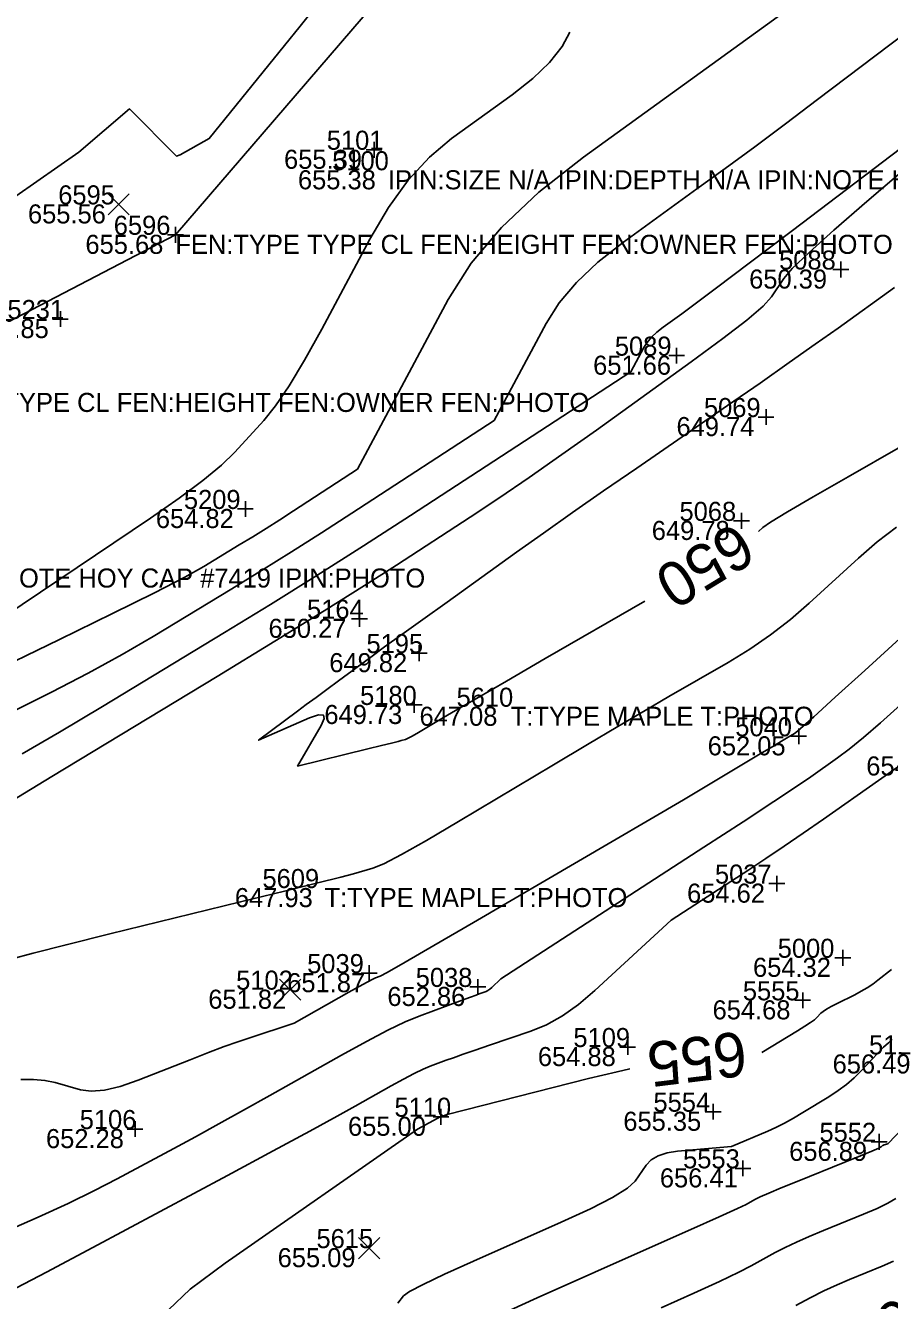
# Model space of a CAD drawing. Extents: x 2129350 to 2137777, y 657588 to 659885.
# Drawn here: x 2132874.7 to 2132929.2, y 658364.2 to 658444.5 of the extents above; entities that cross this region are included whole.
import ezdxf

# ---------------------------------------------------------------- set-up
doc = ezdxf.new("R2010")
doc.units = 0
for name, color, linetype in [('DT_X_Contour_Major', 7, 'Continuous'), ('DT_X_Contour_Minor', 7, 'Continuous'), ('DT_X_TIN_Hull', 7, 'Continuous'), ('SV_X_Random_Point', 7, 'Continuous'), ('SV_X_Shot_Marker', 7, 'Continuous'), ('SV_X_Text_Comment', 7, 'Continuous'), ('SV_X_Text_Elevation', 7, 'Continuous'), ('SV_X_Text_Name', 7, 'Continuous')]:
    doc.layers.add(name, color=color, linetype=linetype)

msp = doc.modelspace()

# ---------------------------------------------------------------- linework, layer by layer
at = {"layer": 'DT_X_Contour_Major'}
for points in [[(2132909.034, 658444.103), (2132908.549, 658443.199), (2132907.762, 658442.202), (2132906.717, 658441.189), (2132905.412, 658440.162), (2132901.587, 658437.401), (2132900.19, 658436.228), (2132898.866, 658434.783), (2132897.617, 658433.064), (2132896.442, 658431.072), (2132893.407, 658425.396), (2132892.326, 658423.439), (2132891.358, 658421.829), (2132890.503, 658420.563), (2132889.761, 658419.643), (2132887.935, 658417.651), (2132887.089, 658416.83), (2132885.919, 658415.864), (2132884.427, 658414.752), (2132882.612, 658413.493), (2132873.389, 658407.28)], [(2132929.501, 658428.031), (2132925.944, 658425.468), (2132924.508, 658424.442), (2132922.869, 658423.287), (2132921.027, 658422.002), (2132918.981, 658420.588), (2132913.255, 658416.643), (2132911.171, 658415.202), (2132909.214, 658413.838), (2132907.384, 658412.55), (2132905.681, 658411.338), (2132901.309, 658408.207), (2132899.778, 658407.11), (2132898.467, 658406.166), (2132897.374, 658405.374), (2132896.501, 658404.736), (2132894.463, 658403.238), (2132893.729, 658402.697), (2132893.054, 658402.199), (2132892.438, 658401.742), (2132891.882, 658401.328), (2132889.427, 658399.493), (2132892.642, 658400.906), (2132893.204, 658401.103), (2132893.515, 658401.087), (2132893.573, 658400.859), (2132893.38, 658400.419), (2132891.888, 658397.868), (2132896.324, 658398.954), (2132897.168, 658399.16), (2132897.799, 658399.316), (2132898.216, 658399.421), (2132898.42, 658399.474), (2132898.679, 658399.547), (2132898.824, 658399.607), (2132899.062, 658399.73), (2132899.395, 658399.918), (2132899.821, 658400.169), (2132901.085, 658400.925), (2132901.84, 658401.37), (2132903.159, 658402.138), (2132905.042, 658403.229), (2132907.487, 658404.643), (2132913.765, 658408.269)], [(2132920.925, 658412.642), (2132921.198, 658412.891), (2132921.693, 658413.236), (2132922.754, 658413.886), (2132924.382, 658414.842), (2132926.576, 658416.102), (2132933.185, 658419.871)], [(2132921.145, 658379.818), (2132923.388, 658381.188), (2132923.849, 658381.476), (2132924.207, 658381.711), (2132924.46, 658381.893), (2132924.609, 658382.023), (2132924.868, 658382.299), (2132925.004, 658382.415), (2132925.22, 658382.557), (2132925.516, 658382.724), (2132925.891, 658382.917), (2132926.996, 658383.467), (2132927.399, 658383.679), (2132927.777, 658383.901), (2132928.131, 658384.136), (2132928.46, 658384.381), (2132929.306, 658385.05)], [(2132883.761, 658363.616), (2132885.126, 658364.908), (2132887.315, 658366.547), (2132899.451, 658375.001), (2132900.909, 658375.784), (2132900.919, 658375.789), (2132900.955, 658375.801), (2132901.317, 658375.924), (2132910.219, 658378.182), (2132912.019, 658378.616), (2132912.833, 658378.788)]]:
    msp.add_lwpolyline(points, dxfattribs=at)
at = {"layer": 'DT_X_Contour_Minor'}
for points in [[(2132892.982, 658445.64), (2132892.047, 658444.483), (2132891.058, 658443.26), (2132886.32, 658437.401), (2132884.495, 658436.388), (2132884.255, 658436.304), (2132881.291, 658439.27), (2132878.094, 658436.551), (2132864.847, 658427.298)], [(2132922.872, 658445.608), (2132920.747, 658444.066), (2132918.013, 658442.089), (2132909.908, 658436.239), (2132907.096, 658434.034), (2132904.737, 658431.803), (2132902.832, 658429.549), (2132901.381, 658427.27), (2132895.666, 658416.58), (2132891.627, 658413.948), (2132890.765, 658413.39), (2132889.91, 658412.847), (2132889.06, 658412.318), (2132888.217, 658411.802), (2132885.977, 658410.446), (2132884.779, 658409.777), (2132882.863, 658408.787), (2132880.229, 658407.477), (2132876.878, 658405.845), (2132866.986, 658401.067)], [(2132930.152, 658444.03), (2132924.654, 658439.863), (2132922.632, 658438.339), (2132920.692, 658436.892), (2132918.832, 658435.522), (2132917.053, 658434.229), (2132912.419, 658430.884), (2132910.81, 658429.622), (2132909.461, 658428.347), (2132908.372, 658427.057), (2132907.541, 658425.754), (2132904.273, 658419.64), (2132895.316, 658413.801), (2132893.404, 658412.565), (2132891.506, 658411.36), (2132889.622, 658410.186), (2132887.752, 658409.043), (2132882.784, 658406.034), (2132880.832, 658404.892), (2132878.7, 658403.719), (2132876.39, 658402.518), (2132873.901, 658401.287)], [(2132937.291, 658442.399), (2132923.065, 658431.62), (2132920.343, 658429.559), (2132918.274, 658427.997), (2132916.858, 658426.934), (2132916.094, 658426.369), (2132914.929, 658425.528), (2132914.524, 658425.21), (2132914.185, 658424.89), (2132913.911, 658424.565), (2132913.702, 658424.238), (2132912.88, 658422.7), (2132899.005, 658413.654), (2132896.043, 658411.74), (2132893.102, 658409.873), (2132890.183, 658408.054), (2132887.287, 658406.283), (2132879.591, 658401.623), (2132876.885, 658400.006), (2132874.538, 658398.651)], [(2132933.961, 658438.742), (2132927.752, 658433.434), (2132925.679, 658431.638), (2132924.115, 658430.231), (2132923.062, 658429.213), (2132922.518, 658428.584), (2132921.748, 658427.426), (2132921.216, 658426.845), (2132920.196, 658425.97), (2132918.688, 658424.8), (2132916.692, 658423.337), (2132910.72, 658419.042), (2132908.542, 658417.49), (2132906.49, 658416.058), (2132904.563, 658414.745), (2132902.76, 658413.551), (2132898.12, 658410.526), (2132896.108, 658409.237), (2132893.555, 658407.641), (2132890.459, 658405.736), (2132886.821, 658403.523), (2132876.398, 658397.211), (2132872.938, 658395.121)], [(2132873.823, 658385.71), (2132875.222, 658386.088), (2132877.299, 658386.617), (2132880.053, 658387.297), (2132888.3, 658389.315), (2132891.064, 658389.993), (2132893.169, 658390.514), (2132894.617, 658390.88), (2132895.406, 658391.088), (2132896.632, 658391.435), (2132897.315, 658391.717), (2132898.443, 658392.301), (2132900.017, 658393.189), (2132902.036, 658394.379), (2132908.014, 658397.957), (2132910.15, 658399.232), (2132912.074, 658400.372), (2132913.787, 658401.379), (2132915.288, 658402.252), (2132919.01, 658404.402), (2132920.377, 658405.24), (2132921.686, 658406.142), (2132922.937, 658407.108), (2132924.13, 658408.138), (2132927.236, 658410.97), (2132928.413, 658411.989), (2132929.616, 658412.924)], [(2132874.445, 658378.115), (2132875.249, 658378.128), (2132875.971, 658378.068), (2132876.61, 658377.932), (2132878.203, 658377.473), (2132878.88, 658377.383), (2132879.713, 658377.455), (2132880.704, 658377.691), (2132881.853, 658378.09), (2132885.125, 658379.371), (2132886.275, 658379.816), (2132887.272, 658380.192), (2132888.117, 658380.499), (2132888.808, 658380.736), (2132891.677, 658381.678), (2132895.118, 658383.616), (2132895.777, 658383.985), (2132896.278, 658384.259), (2132896.621, 658384.439), (2132896.806, 658384.526), (2132897.091, 658384.631), (2132897.539, 658384.873), (2132898.669, 658385.518), (2132900.481, 658386.568), (2132902.975, 658388.021), (2132916.208, 658395.746), (2132920.935, 658398.575), (2132921.83, 658399.11), (2132922.487, 658399.503), (2132922.907, 658399.754), (2132923.09, 658399.862), (2132923.26, 658399.96), (2132923.581, 658400.234), (2132924.415, 658400.981), (2132925.763, 658402.202), (2132927.625, 658403.897), (2132933.274, 658409.048)], [(2132873.449, 658368.531), (2132875.547, 658369.455), (2132877.426, 658370.32), (2132879.087, 658371.125), (2132880.53, 658371.87), (2132884.085, 658373.776), (2132885.464, 658374.521), (2132886.932, 658375.325), (2132888.489, 658376.189), (2132890.137, 658377.113), (2132894.649, 658379.654), (2132896.225, 658380.523), (2132897.567, 658381.224), (2132898.677, 658381.758), (2132899.553, 658382.123), (2132902.257, 658383.124), (2132902.775, 658383.314), (2132903.134, 658383.445), (2132903.331, 658383.515), (2132903.645, 658383.621), (2132903.763, 658383.67), (2132903.883, 658383.737), (2132904.004, 658383.823), (2132904.127, 658383.928), (2132904.703, 658384.459), (2132917.479, 658392.756), (2132919.954, 658394.367), (2132921.903, 658395.644), (2132923.325, 658396.589), (2132924.222, 658397.199), (2132925.912, 658398.384), (2132926.635, 658398.926), (2132927.538, 658399.666), (2132928.62, 658400.603), (2132929.881, 658401.736)], [(2132873.685, 658364.746), (2132876.068, 658365.983), (2132878.982, 658367.532), (2132887.463, 658372.08), (2132890.351, 658373.632), (2132892.657, 658374.877), (2132894.379, 658375.815), (2132895.519, 658376.446), (2132897.779, 658377.719), (2132898.569, 658378.154), (2132899.241, 658378.506), (2132899.797, 658378.773), (2132900.236, 658378.956), (2132901.25, 658379.331), (2132901.706, 658379.496), (2132902.312, 658379.709), (2132903.068, 658379.969), (2132903.974, 658380.277), (2132906.59, 658381.163), (2132907.578, 658381.572), (2132908.578, 658382.136), (2132909.591, 658382.855), (2132910.617, 658383.729), (2132915.435, 658388.166), (2132920.324, 658391.342), (2132921.403, 658392.051), (2132922.546, 658392.818), (2132923.751, 658393.642), (2132925.018, 658394.523), (2132928.483, 658396.951), (2132929.683, 658397.805)], [(2132929.346, 658380.644), (2132929.112, 658380.443), (2132928.812, 658380.152), (2132928.447, 658379.772), (2132927.386, 658378.64), (2132926.961, 658378.222), (2132926.482, 658377.816), (2132925.949, 658377.422), (2132925.362, 658377.041), (2132923.726, 658376.041), (2132923.127, 658375.687), (2132922.559, 658375.374), (2132922.022, 658375.104), (2132921.516, 658374.875), (2132919.225, 658373.903), (2132915.835, 658373.605), (2132915.167, 658373.502), (2132914.614, 658373.321), (2132914.177, 658373.061), (2132913.857, 658372.723), (2132913.157, 658371.718), (2132912.668, 658371.274), (2132911.728, 658370.694), (2132910.337, 658369.979), (2132908.495, 658369.129), (2132902.979, 658366.682), (2132901.152, 658365.857), (2132899.809, 658365.217), (2132898.948, 658364.763), (2132898.57, 658364.494), (2132898.206, 658364.024)], [(2132931.643, 658376.746), (2132929.074, 658374.066), (2132928.858, 658374.005), (2132928.815, 658373.991), (2132928.778, 658373.974), (2132928.747, 658373.956), (2132928.722, 658373.934), (2132928.663, 658373.875), (2132928.504, 658373.799), (2132928.069, 658373.614), (2132927.358, 658373.321), (2132926.372, 658372.92), (2132923.376, 658371.706), (2132922.366, 658371.293), (2132921.585, 658370.964), (2132921.031, 658370.721), (2132920.706, 658370.562), (2132920.143, 658370.251), (2132919.616, 658369.998), (2132918.461, 658369.471), (2132916.675, 658368.67), (2132914.26, 658367.596), (2132906.98, 658364.366), (2132904.556, 658363.26)], [(2132929.574, 658370.617), (2132929.078, 658370.329), (2132928.402, 658370.003), (2132927.546, 658369.639), (2132925.024, 658368.617), (2132924.125, 658368.242), (2132923.32, 658367.885), (2132922.609, 658367.545), (2132921.991, 658367.221), (2132920.47, 658366.382), (2132919.687, 658365.981), (2132918.479, 658365.407), (2132916.847, 658364.66), (2132914.79, 658363.739)], [(2132929.446, 658366.686), (2132928.72, 658366.359), (2132926.672, 658365.529), (2132925.884, 658365.192), (2132925.055, 658364.806), (2132924.186, 658364.368), (2132923.277, 658363.881)]]:
    msp.add_lwpolyline(points, dxfattribs=at)
at = {"layer": 'DT_X_TIN_Hull'}
msp.add_lwpolyline([(2132540.53, 658289.401), (2132539.033, 658286.057), (2132536.832, 658279.3), (2132537.201, 658279.007), (2132540.621, 658270.415), (2132548.203, 658269.845), (2132579.386, 658310.868), (2132621.001, 658329.414), (2132667.619, 658335.399), (2132712.749, 658350.209), (2132765.513, 658370.931), (2132811.121, 658416.764), (2132865.063, 658421.381), (2132884.187, 658431.342), (2132933.332, 658488.426), (2132983.351, 658480.409), (2133063.13, 658518.414), (2133131.969, 658559.405), (2133180.891, 658556.239), (2133241.37, 658575.534)], dxfattribs=at)
at = {"layer": 'SV_X_Random_Point'}
for p, q in [((2132879.948, 658432.59), (2132881.282, 658433.926)), ((2132879.948, 658433.926), (2132881.282, 658432.59)), ((2132890.752, 658383.115), (2132892.086, 658384.451)), ((2132890.752, 658384.451), (2132892.086, 658383.115)), ((2132895.728, 658366.833), (2132897.062, 658368.167)), ((2132895.728, 658368.167), (2132897.062, 658366.833))]:
    msp.add_line(p, q, dxfattribs=at)
at = {"layer": 'SV_X_Shot_Marker'}
for p, q in [((2132896.704, 658437.2), (2132896.704, 658436.2)), ((2132896.204, 658436.7), (2132897.204, 658436.7)), ((2132896.704, 658436.7), (2132896.704, 658436.7)), ((2132883.689, 658431.342), (2132884.689, 658431.342)), ((2132884.189, 658431.842), (2132884.189, 658430.842)), ((2132884.189, 658431.342), (2132884.189, 658431.342)), ((2132926.123, 658429.654), (2132926.123, 658428.654)), ((2132925.623, 658429.154), (2132926.623, 658429.154)), ((2132926.123, 658429.154), (2132926.123, 658429.154)), ((2132876.942, 658426.536), (2132876.942, 658425.536)), ((2132876.442, 658426.036), (2132877.442, 658426.036)), ((2132876.942, 658426.036), (2132876.942, 658426.036)), ((2132915.772, 658424.228), (2132915.772, 658423.228)), ((2132915.272, 658423.728), (2132916.272, 658423.728)), ((2132915.772, 658423.728), (2132915.772, 658423.728)), ((2132921.404, 658420.36), (2132921.404, 658419.36)), ((2132920.904, 658419.86), (2132921.904, 658419.86)), ((2132921.404, 658419.86), (2132921.404, 658419.86)), ((2132888.599, 658414.568), (2132888.599, 658413.568)), ((2132888.099, 658414.068), (2132889.099, 658414.068)), ((2132888.599, 658414.068), (2132888.599, 658414.068)), ((2132919.864, 658413.816), (2132919.864, 658412.816)), ((2132919.364, 658413.316), (2132920.364, 658413.316)), ((2132919.864, 658413.316), (2132919.864, 658413.316)), ((2132895.29, 658407.15), (2132896.29, 658407.15)), ((2132895.79, 658407.65), (2132895.79, 658406.65)), ((2132895.79, 658407.15), (2132895.79, 658407.15)), ((2132899.544, 658405.487), (2132899.544, 658404.487)), ((2132899.044, 658404.987), (2132900.044, 658404.987)), ((2132899.544, 658404.987), (2132899.544, 658404.987)), ((2132898.728, 658401.721), (2132899.728, 658401.721)), ((2132899.228, 658402.221), (2132899.228, 658401.221)), ((2132899.228, 658401.721), (2132899.228, 658401.721)), ((2132923.464, 658400.247), (2132923.464, 658399.247)), ((2132922.964, 658399.747), (2132923.964, 658399.747)), ((2132923.464, 658399.747), (2132923.464, 658399.747)), ((2132921.588, 658390.465), (2132922.588, 658390.465)), ((2132922.088, 658390.965), (2132922.088, 658389.965)), ((2132922.088, 658390.465), (2132922.088, 658390.465)), ((2132926.244, 658386.291), (2132926.244, 658385.291)), ((2132925.744, 658385.791), (2132926.744, 658385.791)), ((2132926.244, 658385.791), (2132926.244, 658385.791)), ((2132895.904, 658384.825), (2132896.904, 658384.825)), ((2132896.404, 658385.325), (2132896.404, 658384.325)), ((2132896.404, 658384.825), (2132896.404, 658384.825)), ((2132902.744, 658383.955), (2132903.744, 658383.955)), ((2132903.244, 658384.455), (2132903.244, 658383.455)), ((2132903.244, 658383.955), (2132903.244, 658383.955)), ((2132923.215, 658383.112), (2132924.215, 658383.112)), ((2132923.715, 658383.612), (2132923.715, 658382.612)), ((2132923.715, 658383.112), (2132923.715, 658383.112)), ((2132912.688, 658380.669), (2132912.688, 658379.669)), ((2132912.188, 658380.169), (2132913.188, 658380.169)), ((2132912.688, 658380.169), (2132912.688, 658380.169)), ((2132918.072, 658376.593), (2132918.072, 658375.593)), ((2132900.422, 658375.776), (2132901.422, 658375.776)), ((2132900.922, 658376.276), (2132900.922, 658375.276)), ((2132900.922, 658375.776), (2132900.922, 658375.776)), ((2132917.572, 658376.093), (2132918.572, 658376.093)), ((2132918.072, 658376.093), (2132918.072, 658376.093)), ((2132881.147, 658375.001), (2132882.147, 658375.001)), ((2132881.647, 658375.501), (2132881.647, 658374.501)), ((2132881.647, 658375.001), (2132881.647, 658375.001)), ((2132928.032, 658374.197), (2132929.032, 658374.197)), ((2132928.532, 658374.697), (2132928.532, 658373.697)), ((2132928.532, 658374.197), (2132928.532, 658374.197)), ((2132919.95, 658373.026), (2132919.95, 658372.026)), ((2132919.45, 658372.526), (2132920.45, 658372.526)), ((2132919.95, 658372.526), (2132919.95, 658372.526))]:
    msp.add_line(p, q, dxfattribs=at)

# ---------------------------------------------------------------- texts
at = {"layer": 'DT_X_Contour_Major'}
for s, rotation, p in [('650', 211.41516, (2132919.508, 658413.309)), ('655', 187.05856, (2132919.996, 658381.177)), ('660', 214.83167, (2132933.196, 658366.941))]:
    msp.add_text(s, height=2.8, rotation=rotation, dxfattribs=at).set_placement(p)
at = {"layer": 'SV_X_Text_Comment'}
for s, p in [('IPIN:SIZE N/A IPIN:DEPTH N/A IPIN:NOTE HOY CAP #7419 IPIN:PHOTO', (2132897.58, 658434.208)), ('FEN:TYPE TYPE CL FEN:HEIGHT FEN:OWNER FEN:PHOTO', (2132884.189, 658430.142)), ('FEN:TYPE TYPE CL FEN:HEIGHT FEN:OWNER FEN:PHOTO', (2132865.065, 658420.182)), ('IPIN:SIZE N/A IPIN:DEPTH N/A IPIN:NOTE HOY CAP #7419 IPIN:PHOTO', (2132846.339, 658409.117)), ('T:TYPE MAPLE T:PHOTO', (2132905.325, 658400.409)), ('T:TYPE MAPLE T:PHOTO', (2132893.587, 658388.985))]:
    msp.add_text(s, height=1.2, dxfattribs=at).set_placement(p)
at = {"layer": 'SV_X_Text_Elevation'}
for s, p in [('655.39', (2132891.035, 658435.5)), ('655.38', (2132891.911, 658434.208)), ('655.56', (2132874.899, 658432.058)), ('655.68', (2132878.52, 658430.142)), ('650.39', (2132920.341, 658427.954)), ('655.85', (2132871.301, 658424.836)), ('651.66', (2132910.51, 658422.528)), ('649.74', (2132915.763, 658418.66)), ('654.82', (2132882.958, 658412.868)), ('649.78', (2132914.205, 658412.116)), ('650.27', (2132890.055, 658405.95)), ('649.82', (2132893.885, 658403.787)), ('649.73', (2132893.578, 658400.521)), ('647.08', (2132899.571, 658400.409)), ('652.05', (2132917.729, 658398.547)), ('654.59', (2132927.722, 658397.278)), ('654.62', (2132916.429, 658389.265)), ('647.93', (2132887.937, 658388.985)), ('654.32', (2132920.585, 658384.591)), ('651.87', (2132891.236, 658383.625)), ('651.82', (2132886.261, 658382.583)), ('652.86', (2132897.547, 658382.755)), ('654.68', (2132918.037, 658381.912)), ('654.88', (2132907.029, 658378.969)), ('656.49', (2132925.601, 658378.504)), ('655.00', (2132895.064, 658374.576)), ('655.35', (2132912.413, 658374.893)), ('652.28', (2132876.035, 658373.801)), ('656.89', (2132922.863, 658372.997)), ('656.41', (2132914.715, 658371.326)), ('655.09', (2132890.632, 658366.3))]:
    msp.add_text(s, height=1.2, dxfattribs=at).set_placement(p)
at = {"layer": 'SV_X_Text_Name'}
for s, p in [('5101', (2132893.728, 658436.7)), ('5100', (2132894.066, 658435.408)), ('6595', (2132876.807, 658433.258)), ('6596', (2132880.306, 658431.342)), ('5088', (2132922.23, 658429.154)), ('5231', (2132873.606, 658426.036)), ('5089', (2132911.879, 658423.728)), ('5069', (2132917.492, 658419.86)), ('5209', (2132884.725, 658414.068)), ('5068', (2132915.952, 658413.316)), ('5164', (2132892.484, 658407.15)), ('5195', (2132896.228, 658404.987)), ('5180', (2132895.827, 658401.721)), ('5610', (2132901.905, 658401.609)), ('5040', (2132919.467, 658399.747)), ('5609', (2132889.675, 658390.185)), ('5037', (2132918.186, 658390.465)), ('5000', (2132922.143, 658385.791)), ('5039', (2132892.492, 658384.825)), ('5102', (2132888.018, 658383.783)), ('5038', (2132899.332, 658383.955)), ('5555', (2132919.945, 658383.112)), ('5109', (2132909.268, 658380.169)), ('5120', (2132927.897, 658379.704)), ('5110', (2132897.994, 658375.776)), ('5554', (2132914.312, 658376.093)), ('5106', (2132878.161, 658375.001)), ('5552', (2132924.772, 658374.197)), ('5553', (2132916.18, 658372.526)), ('5615', (2132893.079, 658367.5))]:
    msp.add_text(s, height=1.2, dxfattribs=at).set_placement(p)

doc.saveas('drawing.dxf')
